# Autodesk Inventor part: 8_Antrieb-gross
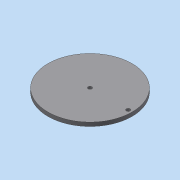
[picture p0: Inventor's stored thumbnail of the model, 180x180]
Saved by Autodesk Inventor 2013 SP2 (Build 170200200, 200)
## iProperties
Created: 2014-01
Part Number: 8_Antrieb-gross
Material: Allgemein
Document SubType Name: Modeling
Designer: J. Palme
Density: 1 g/cm^3
Author: J. Palme
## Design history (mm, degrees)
sketch "Skizze1"
  geometry: C1 r 0.5 at (0, 0); C2 r 0.5 at (10, 0); C3 r 11 at (0, 0); 1 further point
  constraints: 3 centre point, 2 coincident, 1 equal radius, 1 horizontal alignment
  dimensions: "d0" = 10 distance of C2.centre C1.centre; "d5" = 1 diameter of C1; "d6" = 22 diameter of C3
extrude "Extrusion1" new body sketch "Skizze1" distance "d2" = 1; taper "d3" = 0 deg
node "Volumenkörper1"
